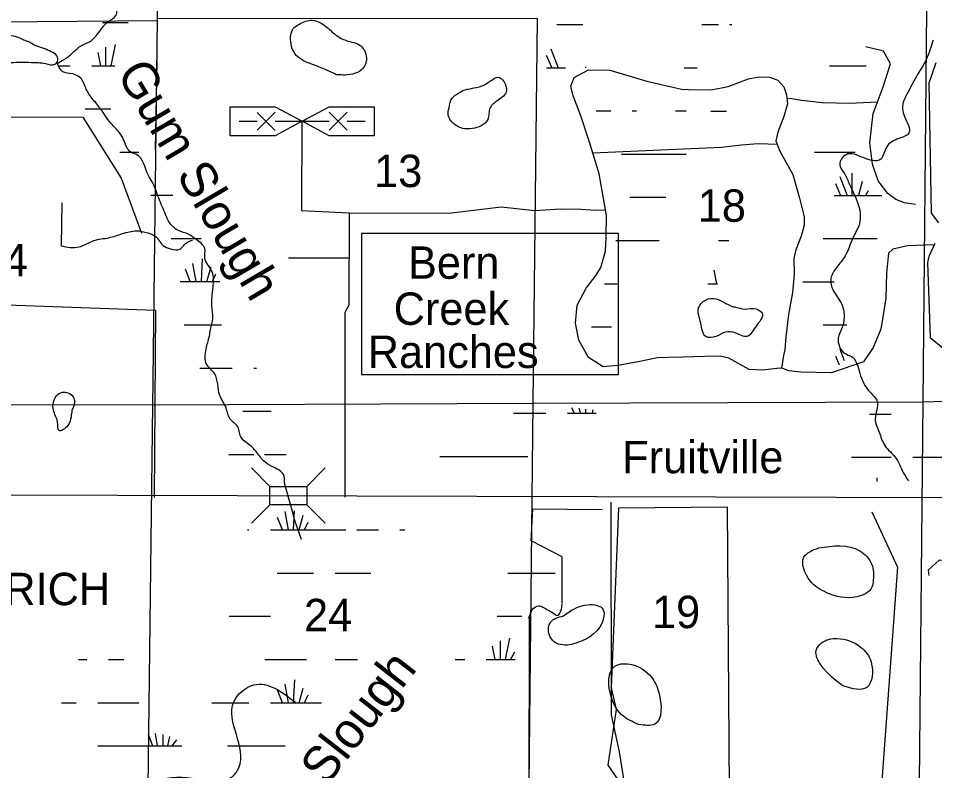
# Model space of a CAD drawing. Extents: x 408847 to 817539, y 923858 to 1151780.
# Drawn here: x 535062 to 547799, y 1088654 to 1099108 of the extents above; entities that cross this region are included whole.
import ezdxf

# ---------------------------------------------------------------- set-up
doc = ezdxf.new("R2010")
doc.units = 0
for name, color, linetype in [('Bridges', 7, 'Continuous'), ('County Roads Related Text', 7, 'Continuous'), ('County Routes Highway Center Lines', 7, 'Continuous'), ('Lakes and Ponds', 7, 'Continuous'), ('Level 39', 7, 'Continuous'), ('Level 43', 7, 'Continuous'), ('Level 47', 7, 'Continuous'), ('Local Roads Improved', 7, 'Continuous'), ('Local Roads Paved', 7, 'Continuous'), ('Local Roads Related Cells', 7, 'Continuous'), ('Masks for Text', 7, 'Continuous'), ('Narrow River Creek and Branch and Slough', 7, 'Continuous'), ('Section Lines', 7, 'Continuous'), ('Swamps', 7, 'Continuous'), ('Township  and Range lines', 7, 'Continuous')]:
    doc.layers.add(name, color=color, linetype=linetype)

msp = doc.modelspace()

# ---------------------------------------------------------------- linework, layer by layer
at = {"layer": 'Bridges'}
for p, q in [((538560, 1092604), (538304, 1092860)), ((539072, 1092604), (539328, 1092860)), ((538560, 1092348), (538304, 1092092)), ((539072, 1092348), (539328, 1092092))]:
    msp.add_line(p, q, dxfattribs=at)
msp.add_lwpolyline([(538560, 1092604), (539072, 1092604), (539072, 1092348), (538560, 1092348)], close=True, dxfattribs=at)
at = {"layer": 'County Routes Highway Center Lines'}
msp.add_line((534492, 1092489), (550075, 1092446), dxfattribs=at)
at = {"layer": 'Lakes and Ponds'}
for points in [[(539482, 1098325), (539576, 1098320), (539706, 1098332), (539814, 1098377), (539900, 1098529), (539821, 1098725), (539619, 1098800), (539472, 1098880), (539336, 1098996), (539147, 1099081), (538969, 1099028), (538883, 1098966), (538850, 1098880), (538852, 1098752), (538903, 1098620), (539007, 1098530), (539171, 1098460), (539318, 1098401), (539482, 1098325)], [(534540, 1098010), (534605, 1098098), (534657, 1098204), (534683, 1098304), (534760, 1098433), (534922, 1098487), (535070, 1098500), (535239, 1098495), (535439, 1098479), (535571, 1098470), (535609, 1098526), (535582, 1098604), (535496, 1098654), (535388, 1098699), (535280, 1098737), (535216, 1098777), (535177, 1098791), (535021, 1098854), (534895, 1098882), (534801, 1098972), (534682, 1099053), (534586, 1099055), (534439, 1099058)], [(541049, 1097864), (541037, 1097762), (541101, 1097656), (541236, 1097579), (541374, 1097577), (541496, 1097614), (541586, 1097704), (541619, 1097864), (541731, 1097969), (541846, 1098105), (541722, 1098289), (541642, 1098251), (541542, 1098186), (541394, 1098140), (541272, 1098115), (541152, 1098051), (541092, 1097999), (541049, 1097864)], [(544868, 1095163), (544759, 1095212), (544615, 1095194), (544518, 1095085), (544548, 1094871), (544619, 1094685), (544759, 1094686), (544893, 1094748), (545027, 1094737), (545190, 1094687), (545307, 1094816), (545399, 1095014), (545318, 1095070), (545164, 1095068), (545046, 1095091), (544988, 1095105), (544868, 1095163)], [(535807, 1093664), (535843, 1093794), (535784, 1093889), (535641, 1093901), (535558, 1093806), (535546, 1093687), (535570, 1093604), (535606, 1093498), (535629, 1093379), (535748, 1093450), (535795, 1093569), (535807, 1093664)], [(546187, 1091751), (545981, 1091621), (546068, 1091293), (546297, 1091127), (546716, 1091069), (546927, 1091202), (546945, 1091304), (546926, 1091520), (546757, 1091710), (546187, 1091751)], [(542640, 1090805), (542456, 1090714), (542463, 1090498), (542571, 1090414), (542811, 1090425), (543196, 1090773), (543192, 1090891), (542976, 1090960), (542640, 1090805)], [(546524, 1089831), (546856, 1089812), (546917, 1090160), (546770, 1090372), (546441, 1090491), (546227, 1090430), (546152, 1090324), (546220, 1090120), (546524, 1089831)], [(543683, 1089298), (543910, 1089301), (543966, 1089739), (543863, 1089953), (543560, 1090134), (543334, 1090090), (543281, 1089983), (543286, 1089743), (543447, 1089431), (543683, 1089298)]]:
    msp.add_spline(points, degree=3, dxfattribs=at)
at = {"layer": 'Level 39'}
msp.add_line((536985, 1098507), (536963, 1097279), dxfattribs=at)
at = {"layer": 'Local Roads Improved'}
for p, q in [((539002, 1097666), (538998, 1096437)), ((538998, 1096437), (539659, 1096404)), ((539659, 1096391), (539657, 1095122)), ((539657, 1095122), (539599, 1095020)), ((539599, 1095020), (539600, 1092453))]:
    msp.add_line(p, q, dxfattribs=at)
for points in [[(543236, 1096367), (543137, 1096949), (543001, 1097388), (542880, 1097753), (542772, 1098032), (542740, 1098165), (542787, 1098288), (542989, 1098393), (543284, 1098388), (543796, 1098234), (544282, 1098122), (544376, 1098120), (544693, 1098115), (544930, 1098160), (545211, 1098268), (545354, 1098297), (545506, 1098290), (545619, 1098249), (545701, 1098155), (545741, 1098043), (545755, 1097918), (545704, 1097743), (545617, 1097526), (545589, 1097406), (545648, 1097260), (545827, 1096940), (545919, 1096610), (545985, 1096350), (545986, 1096233), (545941, 1096079), (545867, 1095892), (545843, 1095773), (545846, 1095548), (545823, 1095298), (545768, 1094992), (545729, 1094682), (545717, 1094507), (545699, 1094422), (545669, 1094245)], [(539659, 1096404), (541044, 1096401), (541771, 1096487), (542240, 1096437), (542598, 1096462), (542880, 1096455), (543088, 1096441), (543222, 1096449)], [(547793, 1095963), (547423, 1095946), (547217, 1095900), (547155, 1095845), (547130, 1095566), (547119, 1095221), (547049, 1094788), (546946, 1094533), (546810, 1094333), (546363, 1094181), (545940, 1094190), (545773, 1094210), (545690, 1094243), (545646, 1094249), (545404, 1094220), (545221, 1094228), (544936, 1094387), (544818, 1094416), (544601, 1094408), (544301, 1094399), (544095, 1094396), (543945, 1094391), (543678, 1094336), (543399, 1094282), (543193, 1094267), (542986, 1094393), (542855, 1094634), (542806, 1094871), (542831, 1095123), (542953, 1095358), (543094, 1095538), (543157, 1095646), (543223, 1095872), (543234, 1096061), (543236, 1096367)], [(540130, 1076628), (540280, 1076888), (540490, 1077328), (540709, 1077606), (541309, 1078329), (541599, 1078701), (542129, 1079236), (542612, 1079677), (543029, 1080268), (543264, 1080644), (543418, 1081052), (543428, 1081406), (543456, 1086045), (543526, 1087142), (543550, 1087725), (543519, 1088277), (543418, 1088915), (543306, 1089429), (543303, 1092386)]]:
    msp.add_lwpolyline(points, dxfattribs=at)
at = {"layer": 'Local Roads Paved'}
for p, q in [((539002, 1097666), (538998, 1096437)), ((538998, 1096437), (539659, 1096404)), ((539659, 1096391), (539657, 1095122)), ((539659, 1096404), (539659, 1096391)), ((539658, 1095776), (538818, 1095776)), ((534308, 1095146), (536967, 1095053)), ((536967, 1095053), (536948, 1092448)), ((539657, 1095122), (539599, 1095020)), ((539599, 1095020), (539600, 1092453))]:
    msp.add_line(p, q, dxfattribs=at)
for points in [[(547532, 1096523), (547380, 1096546), (547259, 1096589), (547146, 1096676), (547014, 1096850), (546933, 1097083), (546898, 1097378), (546945, 1097786), (547083, 1098155), (547183, 1098474), (547086, 1098651), (546840, 1098714)], [(547817, 1098491), (547717, 1098206), (547750, 1096401), (547851, 1096266)], [(545746, 1097998), (545815, 1097995), (545950, 1097973), (546234, 1097937), (546617, 1097930), (547005, 1097947)], [(543046, 1097241), (544835, 1097319), (545110, 1097349), (545345, 1097371), (545608, 1097359)], [(547801, 1095981), (547717, 1095797), (547700, 1095713), (547734, 1094674), (548823, 1093785)], [(548832, 1092439), (548659, 1091699), (548487, 1091570), (548270, 1091548), (547862, 1091579), (547707, 1091438), (547716, 1091365)]]:
    msp.add_lwpolyline(points, dxfattribs=at)
at = {"layer": 'Local Roads Related Cells'}
for p, q in [((538006, 1097877), (538631, 1097877)), ((538006, 1097477), (538006, 1097877)), ((538631, 1097877), (539006, 1097677)), ((539006, 1097677), (539381, 1097877)), ((539381, 1097877), (540006, 1097877)), ((540006, 1097877), (540006, 1097477)), ((538631, 1097802), (538381, 1097552)), ((538381, 1097799), (538631, 1097549)), ((539631, 1097802), (539381, 1097552)), ((539381, 1097802), (539631, 1097552)), ((538131, 1097677), (538381, 1097677)), ((539006, 1097677), (538631, 1097477)), ((538631, 1097677), (539381, 1097677)), ((539381, 1097477), (539006, 1097677)), ((539631, 1097677), (539881, 1097677)), ((538631, 1097477), (538006, 1097477)), ((540006, 1097477), (539381, 1097477))]:
    msp.add_line(p, q, dxfattribs=at)
at = {"layer": 'Masks for Text'}
msp.add_lwpolyline([(539830, 1094160), (543402, 1094160), (543402, 1096117), (539830, 1096117)], close=True, dxfattribs=at)
at = {"layer": 'Narrow River Creek and Branch and Slough'}
for p, q in [((535665, 1096542), (535655, 1095947)), ((538845, 1092351), (538762, 1092655))]:
    msp.add_line(p, q, dxfattribs=at)
for points in [[(534485, 1097740), (535960, 1097736), (536489, 1096885), (536776, 1096125)], [(542621, 1090988), (542619, 1091627), (542192, 1091846), (542212, 1092294), (543179, 1092282)], [(544945, 1088383), (544920, 1092316), (543405, 1092300), (543301, 1089807), (543370, 1089505), (543257, 1088732), (543502, 1088374), (547619, 1088391)], [(546926, 1092249), (547281, 1091483), (547055, 1088385)], [(542164, 1088243), (542165, 1090788)]]:
    msp.add_lwpolyline(points, dxfattribs=at)
for points in [[(535603, 1098482), (535739, 1098564), (535834, 1098645), (535958, 1098741), (536040, 1098776), (536156, 1098882), (536319, 1099069), (536417, 1099147), (536358, 1099448), (536353, 1099712), (536344, 1099964), (536353, 1100379), (536432, 1100597), (536545, 1100908), (536632, 1101255), (536683, 1101743), (536687, 1102070), (536706, 1102396), (536789, 1102749), (536892, 1103005), (536909, 1103368), (536959, 1103570), (536999, 1103949), (537057, 1104189), (537436, 1104367), (537730, 1104538), (537996, 1104699), (538128, 1104726), (538308, 1104688), (538548, 1104799), (538936, 1104881), (539125, 1104956), (539127, 1105236), (539146, 1105342), (539278, 1105475), (539335, 1105609), (539461, 1105798)], [(547776, 1098803), (547681, 1098535), (547544, 1098298), (547409, 1098045), (547361, 1097939), (547378, 1097745), (547442, 1097515), (547301, 1097438), (547133, 1097323), (547049, 1097151), (546803, 1097172), (546567, 1097213), (546479, 1097077), (546544, 1096953), (546614, 1096801), (546764, 1096387), (546754, 1096259), (546675, 1096084), (546565, 1095828), (546452, 1095667), (546362, 1095516), (546377, 1095350), (546486, 1095175), (546540, 1094993), (546511, 1094810), (546457, 1094636), (546572, 1094440), (546668, 1094394), (546686, 1094370), (546781, 1094110), (546900, 1093915), (547001, 1093783), (546973, 1093546), (547026, 1093358), (547105, 1093174), (547263, 1092993), (547384, 1092759), (547437, 1092683)], [(538762, 1092655), (538746, 1092770), (538608, 1092870), (538487, 1092944), (538379, 1093073), (538271, 1093183), (538162, 1093277), (538112, 1093431), (538007, 1093539), (537949, 1093695), (537862, 1093869), (537787, 1094173), (537680, 1094300), (537672, 1094511), (537717, 1094691), (537735, 1094785), (537764, 1094939), (537752, 1095114), (537769, 1095368), (537754, 1095586), (537655, 1095780), (537653, 1095908), (537532, 1096036), (537432, 1096106), (537286, 1096161), (537159, 1096275), (537109, 1096381), (537014, 1096609), (536921, 1096835), (536865, 1096933), (536706, 1097214), (536634, 1097242), (536525, 1097420), (536469, 1097516), (536350, 1097648), (536191, 1097869), (536075, 1098013), (535998, 1098143), (535950, 1098251), (535813, 1098336), (535681, 1098366), (535603, 1098482)], [(535655, 1095947), (535906, 1095932), (536111, 1096019), (536321, 1096060), (536509, 1096116), (536705, 1096155), (536860, 1096128), (536976, 1096070), (537074, 1095952), (537177, 1095906), (537307, 1095899), (537361, 1095953), (537414, 1095997), (537482, 1096026)], [(538997, 1091866), (538923, 1092078), (538896, 1092166), (538864, 1092286), (538845, 1092351)], [(542153, 1090774), (542183, 1090842), (542213, 1090901), (542297, 1090945), (542351, 1090927), (542425, 1090885), (542479, 1090857), (542554, 1090812), (542613, 1090904), (542619, 1090976)], [(534446, 1087774), (534554, 1087784), (534998, 1087431), (535372, 1087310), (535857, 1087324), (536100, 1087515), (536506, 1088091), (537063, 1088536), (537628, 1088532), (538042, 1088579), (538126, 1088694), (538058, 1089612), (538336, 1089846), (538913, 1089605)]]:
    msp.add_spline(points, degree=3, dxfattribs=at)
at = {"layer": 'Section Lines'}
for p, q in [((536982, 1104391), (536992, 1099079)), ((547687, 1099231), (547634, 1093780)), ((536992, 1099107), (536928, 1093709)), ((536992, 1099107), (542273, 1099108)), ((531719, 1099037), (536992, 1099079)), ((547634, 1093780), (552947, 1093922)), ((531662, 1093752), (536928, 1093738)), ((536928, 1093738), (536864, 1088430)), ((536928, 1093738), (542215, 1093759)), ((542215, 1093759), (547634, 1093779)), ((547634, 1093780), (547582, 1088488))]:
    msp.add_line(p, q, dxfattribs=at)
at = {"layer": 'Swamps'}
for p, q in [((536275, 1098707), (536275, 1098449)), ((536166, 1098635), (536203, 1098449)), ((542401, 1098597), (542472, 1098431)), ((543446, 1097221), (544046, 1097221)), ((544046, 1097221), (544346, 1097221)), ((546649, 1096958), (546649, 1096647)), ((546420, 1096813), (546490, 1096647)), ((546480, 1096909), (546583, 1096647)), ((546251, 1096047), (547001, 1096047)), ((537535, 1095449), (537488, 1095703)), ((537606, 1095449), (537623, 1095765)), ((537682, 1095449), (537741, 1095653)), ((537450, 1095449), (537384, 1095621)), ((537759, 1095449), (537808, 1095558)), ((544728, 1095607), (544765, 1095421)), ((537584, 1094249), (538034, 1094249)), ((541946, 1093621), (542396, 1093621)), ((546895, 1093610), (547195, 1093610)), ((538484, 1093049), (538784, 1093049)), ((547495, 1093010), (548095, 1093010)), ((538817, 1091999), (538771, 1092254)), ((538732, 1091999), (538666, 1092171)), ((538965, 1091999), (539023, 1092203)), ((539041, 1091999), (539090, 1092108)), ((538566, 1091999), (539616, 1091999)), ((539766, 1091999), (540066, 1091999)), ((541757, 1090458), (541757, 1090199)), ((541890, 1090494), (541831, 1090199)), ((541649, 1090385), (541686, 1090199)), ((539466, 1090199), (539778, 1090199)), ((538888, 1089599), (538905, 1089915)), ((538817, 1089599), (538771, 1089854)), ((538965, 1089599), (539023, 1089803)), ((538732, 1089599), (538666, 1089771)), ((539041, 1089599), (539090, 1089708)), ((538566, 1089599), (539275, 1089599)), ((536166, 1088999), (536766, 1088999))]:
    msp.add_line(p, q, dxfattribs=at)
for points in [[(536234, 1099049), (536590, 1099049)], [(542546, 1099021), (542909, 1099021)], [(544561, 1099021), (544796, 1099021)], [(544946, 1099021), (544978, 1099021)], [(536408, 1098744), (536349, 1098449)], [(542462, 1098683), (542565, 1098421)], [(535619, 1098449), (535784, 1098449)], [(536084, 1098449), (536403, 1098449)], [(546335, 1098447), (546847, 1098447)], [(542402, 1098421), (542667, 1098421)], [(542945, 1098434), (542945, 1098421)], [(544315, 1098421), (544496, 1098421)], [(535990, 1097849), (536349, 1097849)], [(543096, 1097821), (543296, 1097821)], [(543596, 1097821), (543654, 1097821)], [(544197, 1097821), (544346, 1097821)], [(544688, 1097818), (544906, 1097818)], [(536472, 1097249), (536735, 1097249)], [(546129, 1097247), (546692, 1097247)], [(546789, 1096840), (546741, 1096647)], [(546873, 1096709), (546837, 1096647)], [(536904, 1096649), (537211, 1096649)], [(543561, 1096621), (544046, 1096621)], [(544046, 1096621), (544060, 1096621)], [(546401, 1096647), (547065, 1096647)], [(537188, 1096049), (537602, 1096049)], [(543367, 1096021), (543969, 1096021)], [(544796, 1096021), (544938, 1096021)], [(537313, 1095449), (537865, 1095449)], [(543211, 1095421), (543387, 1095421)], [(544646, 1095421), (544779, 1095421)], [(545967, 1095447), (546401, 1095447)], [(537368, 1094849), (537884, 1094849)], [(543030, 1094821), (543308, 1094821)], [(546251, 1094847), (546578, 1094847)], [(546480, 1094509), (546541, 1094355)], [(546420, 1094413), (546470, 1094294)], [(538334, 1094249), (538371, 1094249)], [(538184, 1093649), (538574, 1093649)], [(542696, 1093621), (543092, 1093621)], [(542752, 1093700), (542786, 1093621)], [(542852, 1093689), (542878, 1093621)], [(542945, 1093679), (542945, 1093621)], [(543047, 1093666), (543036, 1093621)], [(537989, 1093049), (538334, 1093049)], [(540922, 1093021), (542146, 1093021)], [(546641, 1093010), (547195, 1093010)], [(546994, 1092721), (546994, 1092670)], [(538888, 1091999), (538902, 1092266)], [(538246, 1091999), (538266, 1091999)], [(540366, 1091999), (540436, 1091999)], [(538658, 1091399), (539166, 1091399)], [(539466, 1091399), (539961, 1091399)], [(541866, 1091399), (542525, 1091399)], [(537993, 1090799), (538566, 1090799)], [(541716, 1090799), (542061, 1090799)], [(541959, 1090299), (541905, 1090199)], [(535900, 1090199), (536016, 1090199)], [(536316, 1090199), (536528, 1090199)], [(538487, 1090199), (539066, 1090199)], [(541135, 1090199), (541266, 1090199)], [(541566, 1090199), (541969, 1090199)], [(535660, 1089599), (535866, 1089599)], [(536166, 1089599), (536736, 1089599)], [(537753, 1089599), (538266, 1089599)], [(536932, 1089000), (536873, 1089154)], [(536966, 1089183), (536965, 1089185)], [(536994, 1088999), (536968, 1089172)], [(537073, 1088999), (537076, 1089158)], [(537140, 1088999), (537167, 1089130)], [(537202, 1088999), (537263, 1089082)], [(536766, 1088999), (537335, 1088999)], [(537968, 1088999), (538772, 1088999)]]:
    msp.add_lwpolyline(points, dxfattribs=at)
at = {"layer": 'Township  and Range lines'}
for p, q in [((542273, 1099106), (542215, 1093759)), ((542215, 1093759), (542157, 1088458))]:
    msp.add_line(p, q, dxfattribs=at)

# ---------------------------------------------------------------- texts
at = {"layer": 'County Roads Related Text'}
msp.add_text('Fruitville', height=450, rotation=360, dxfattribs=at).set_placement((543456, 1092787))
at = {"layer": 'Level 39'}
for s, p in [('Bern', (540478, 1095489)), ('Creek', (540279, 1094849)), ('Ranches', (539919, 1094250))]:
    msp.add_text(s, height=450, rotation=360, dxfattribs=at).set_placement(p)
at = {"layer": 'Level 43'}
for s, p in [('13', (540007, 1096763)), ('18', (544506, 1096281)), ('14', (534524, 1095524)), ('19', (543870, 1090635)), ('24', (539033, 1090592))]:
    msp.add_text(s, height=450, rotation=360, dxfattribs=at).set_placement(p)
at = {"layer": 'Level 47'}
msp.add_text('GOODRICH', height=450, rotation=360, dxfattribs=at).set_placement((533028, 1090954))
at = {"layer": 'Swamps'}
for s, rotation, p in [('Gum Slough', 300.5559, (536419, 1098345)), ('Cow Pen Slough', 52.125, (537560, 1086136))]:
    msp.add_text(s, height=500, rotation=rotation, dxfattribs=at).set_placement(p)

doc.saveas('drawing.dxf')
